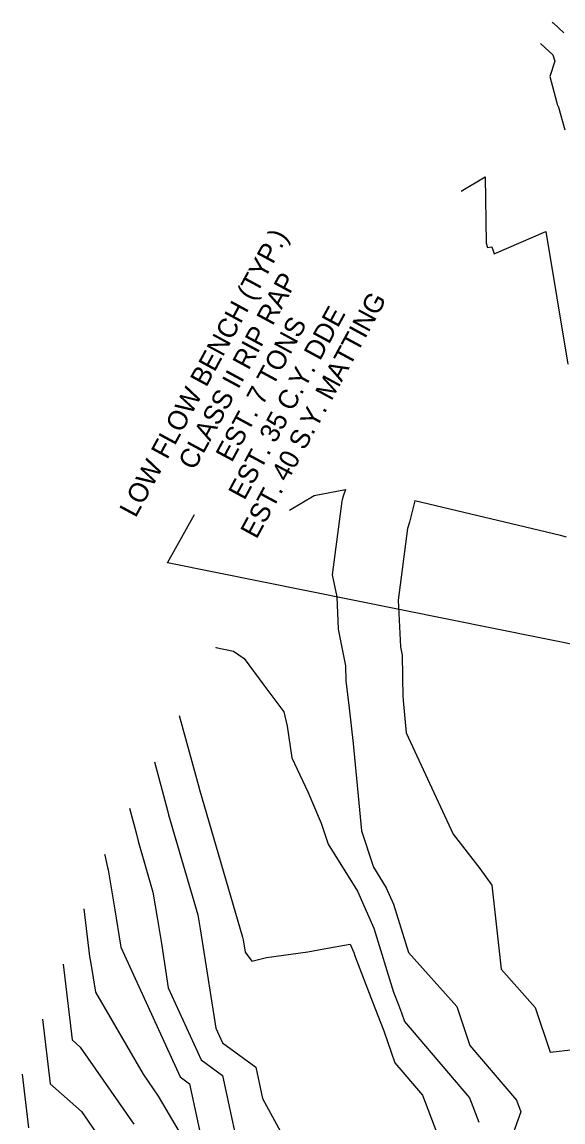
# Model space of a CAD drawing. Extents: x 1368651 to 1378602, y 762048 to 779328.
# Drawn here: x 1376997.1 to 1377080.7, y 762965.4 to 763135.4 of the extents above; entities that cross this region are included whole.
import ezdxf

# ---------------------------------------------------------------- set-up
doc = ezdxf.new("R2010")
doc.units = 0
for name, color, linetype in [('DTM Contours Major', 7, 'Continuous'), ('DTM Contours Minor', 7, 'Continuous'), ('Prop Erosion Rip Rap Class I Label', 7, 'Continuous')]:
    doc.layers.add(name, color=color, linetype=linetype)

msp = doc.modelspace()

# ---------------------------------------------------------------- linework, layer by layer
at = {"layer": 'DTM Contours Major'}
for points in [[(1377079, 763135.44), (1377079.15, 763135.3), (1377080.84, 763133.77)], [(1377021.37, 763028.22), (1377024.45, 763017.01), (1377024.47, 763016.93), (1377031.17, 762993.98), (1377031.21, 762993.75), (1377031.24, 762993.56), (1377031.55, 762991.62), (1377032.59, 762990.24), (1377034.84, 762990.81), (1377041.26, 762991.68), (1377043.74, 762992.17), (1377047.82, 762992.88), (1377048.37, 762991.61), (1377048.54, 762991.07), (1377051.26, 762983.99), (1377053.02, 762979.47), (1377054.71, 762974.54), (1377058.99, 762969.52), (1377061.19, 762963.71)], [(1377003.45, 762989.81), (1377004.83, 762978.11), (1377006.09, 762976.98), (1377014.37, 762965.06)]]:
    msp.add_lwpolyline(points, dxfattribs=at)
at = {"layer": 'DTM Contours Minor'}
for points in [[(1377077.21, 763132.1), (1377077.26, 763132.05), (1377079.12, 763130.37), (1377079.42, 763129.41), (1377078.66, 763127.01), (1377079.7, 763123.14), (1377079.81, 763122.7), (1377080, 763122.29), (1377080.98, 763118.78)], [(1377064.94, 763109.28), (1377068.68, 763111.5), (1377068.82, 763101.25), (1377069.02, 763100.6), (1377069.71, 763100.71), (1377070.03, 763099.62), (1377078.02, 763103.08), (1377081.43, 763082.57)], [(1377038.43, 763059.96), (1377042.24, 763062.22), (1377047.07, 763063.15), (1377046.71, 763062.16), (1377046.56, 763061.58), (1377046.5, 763061.38), (1377045, 763049.98), (1377045.72, 763046.57), (1377045.95, 763041.6), (1377047.07, 763035.93), (1377047.12, 763033.58), (1377047.65, 763029.35), (1377048.27, 763023.88), (1377049.55, 763010.42), (1377051.39, 763004.78), (1377053.38, 763001.6), (1377054.49, 762999.08), (1377056.82, 762991.59), (1377064.27, 762983.26), (1377066.28, 762977.22), (1377073.49, 762968.77), (1377074.16, 762966.98), (1377072.52, 762962.38)], [(1377081.24, 763055.8), (1377080.31, 763056.04), (1377057.77, 763061.41), (1377056.94, 763058.14), (1377056.65, 763057.16), (1377055.22, 763046.06), (1377055.56, 763038.85), (1377055.81, 763037.57), (1377055.94, 763031.03), (1377055.97, 763030.83), (1377056, 763030.57), (1377056.47, 763025.56), (1377063.69, 763009.86), (1377067.85, 763004.56), (1377069.7, 763001.99), (1377071.11, 762989.02), (1377076.39, 762983.11), (1377078.69, 762976.2), (1377082.37, 762976.57)], [(1377027.04, 763038.78), (1377027.05, 763038.73), (1377029.76, 763038.19), (1377031.39, 763037.04), (1377034.45, 763032.9), (1377037.54, 763028.78), (1377038.06, 763026.59), (1377038.79, 763021.71), (1377041.24, 763016.43), (1377043.3, 763011.6), (1377044.37, 763008.34), (1377048.92, 763001.09), (1377051.43, 762995.34), (1377054.5, 762985.48), (1377055.25, 762983.52), (1377055.74, 762982.28), (1377056.2, 762980.91), (1377066.24, 762969.14), (1377067.68, 762965.35)], [(1377017.53, 763021.07), (1377019.59, 763013.55), (1377019.74, 763012.87), (1377024.25, 762997.44), (1377024.62, 762995.23), (1377024.93, 762993.28), (1377027.02, 762979.88), (1377028.04, 762977.64), (1377033.21, 762973.88), (1377034.25, 762969.01), (1377038.24, 762961.65)], [(1377013.68, 763013.93), (1377014.74, 763010.1), (1377015.02, 763008.8), (1377017.32, 763000.91), (1377018.03, 762996.71), (1377018.62, 762992.99), (1377019.69, 762986.14), (1377024.78, 762975), (1377028.09, 762972.59), (1377031.33, 762957.53)], [(1377009.84, 763006.78), (1377009.88, 763006.64), (1377010.3, 763004.73), (1377010.4, 763004.38), (1377011.44, 762998.19), (1377012.31, 762992.71), (1377012.35, 762992.4), (1377021.51, 762972.37), (1377022.97, 762971.3), (1377024.77, 762962.94)], [(1377006.63, 762998.32), (1377007.5, 762990.95), (1377007.66, 762990.21), (1377008.09, 762987.68), (1377008.44, 762985.44), (1377015.78, 762972.77), (1377018.14, 762969.38), (1377022.18, 762962.46)], [(1377000.26, 762981.29), (1377001.44, 762971.29), (1377006.25, 762967), (1377010.6, 762960.73)], [(1376997.08, 762972.78), (1376998.06, 762964.47)]]:
    msp.add_lwpolyline(points, dxfattribs=at)
at = {"layer": 'Prop Erosion Rip Rap Class I Label'}
msp.add_lwpolyline([(1377170.95, 763021.3), (1377019.59, 763051.83), (1377023.75, 763059.33)], dxfattribs=at)

# ---------------------------------------------------------------- texts
for s, p in [('LOW FLOW BENCH (TYP.)', (1377014.63, 763058.67)), ('CLASS II RIP RAP', (1377023.71, 763066)), ('EST. 40 S.Y. MATTING', (1377033.32, 763055.38)), ('EST. 35 C.Y. DDE', (1377031.45, 763061.38)), ('EST. 7 TONS', (1377029.49, 763067.22))]:
    msp.add_text(s, height=3, rotation=61.5756, dxfattribs=at).set_placement(p)

doc.saveas('drawing.dxf')
